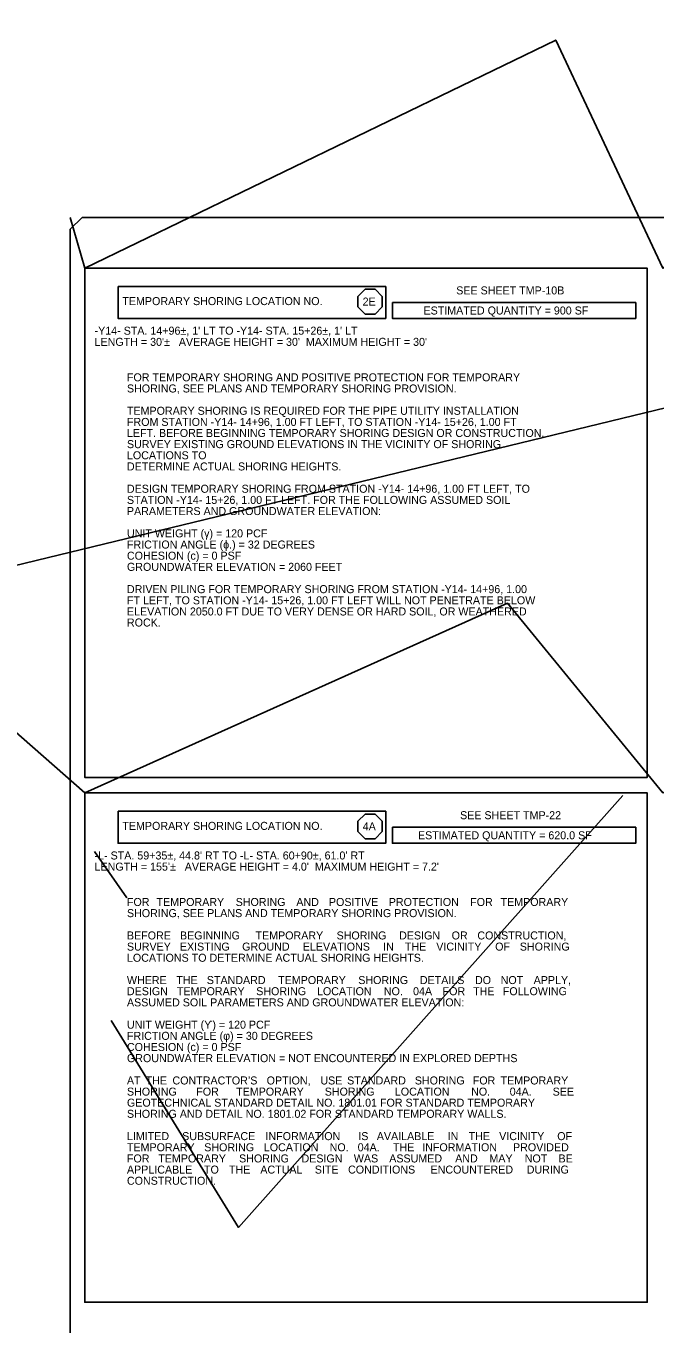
# Model space of a CAD drawing. Extents: x 2487012 to 2497594, y 369516 to 371986.
# Drawn here: x 2490762 to 2491299, y 370340 to 371445 of the extents above; entities that cross this region are included whole.
import ezdxf

# ---------------------------------------------------------------- set-up
doc = ezdxf.new("R2010")
doc.units = 0
for name, color, linetype in [('Scratch_Level_2', 7, 'Continuous'), ('Scratch_Level_3', 7, 'Continuous'), ('Scratch_Level_5', 7, 'Continuous'), ('Scratch_Level_6', 7, 'Continuous'), ('TC LABEL TEMP SHORING', 7, 'Continuous'), ('TC SHEET BORDER LINE THIN', 7, 'Continuous'), ('TC SHEET LAYOUT SHAPE', 7, 'Continuous'), ('TC SHEET TEXT', 7, 'Continuous')]:
    doc.layers.add(name, color=color, linetype=linetype)

msp = doc.modelspace()

# ---------------------------------------------------------------- linework, layer by layer
at = {"layer": 'Scratch_Level_2'}
msp.add_lwpolyline([(2490835.2, 370598.5), (2490943.8, 370422.2), (2491271.3, 370790.1)], dxfattribs=at)
at = {"layer": 'Scratch_Level_3'}
msp.add_line((2490800.3, 371282.3), (2490800.3, 371282.3), dxfattribs=at)
at = {"layer": 'Scratch_Level_5'}
msp.add_line((2490821, 370742.5), (2490848.6, 370702.8), dxfattribs=at)
at = {"layer": 'Scratch_Level_6'}
msp.add_lwpolyline([(2490800.3, 371282.3), (2490812.6, 371239.1), (2491214.2, 371433.4), (2491305.5, 371239.1), (2491620.3, 371445.4), (2491798.4, 371239.1), (2490627, 370955.2), (2490812.6, 370792.3), (2491172.9, 370953.9), (2491305.5, 370792.3), (2491661.6, 370924.6), (2491798.4, 370792.3)], dxfattribs=at)
at = {"layer": 'TC LABEL TEMP SHORING'}
for p, q in [((2491051.6, 371221.2), (2491045.5, 371215)), ((2491060.2, 371221.2), (2491051.6, 371221.2)), ((2491066.3, 371215), (2491060.2, 371221.2)), ((2491045.5, 371215), (2491045.5, 371206.3)), ((2491066.3, 371206.3), (2491066.3, 371215)), ((2491045.5, 371206.3), (2491051.6, 371200.1)), ((2491051.6, 371200.1), (2491060.2, 371200.1)), ((2491060.2, 371200.1), (2491066.3, 371206.3)), ((2491051.6, 370774.3), (2491045.5, 370768.1)), ((2491045.5, 370768.1), (2491045.5, 370759.4)), ((2491060.2, 370774.3), (2491051.6, 370774.3)), ((2491066.3, 370768.1), (2491060.2, 370774.3)), ((2491066.3, 370759.4), (2491066.3, 370768.1)), ((2491045.5, 370759.4), (2491051.6, 370753.2)), ((2491060.2, 370753.2), (2491066.3, 370759.4)), ((2491051.6, 370753.2), (2491060.2, 370753.2))]:
    msp.add_line(p, q, dxfattribs=at)
at = {"layer": 'TC SHEET BORDER LINE THIN'}
for points in [[(2490812.6, 371239.1), (2491292.1, 371239.1), (2491292.1, 370805.5), (2490812.6, 370805.5)], [(2490841.1, 371223.5), (2491069.2, 371223.5), (2491069.2, 371196.3), (2490841.1, 371196.3)], [(2491074.9, 371209.9), (2491282.4, 371209.9), (2491282.4, 371196.3), (2491074.9, 371196.3)], [(2490812.6, 370792.3), (2491292.1, 370792.3), (2491292.1, 370358.6), (2490812.6, 370358.6)], [(2490841.1, 370776.7), (2491069.2, 370776.7), (2491069.2, 370749.4), (2490841.1, 370749.4)], [(2491074.9, 370763), (2491282.4, 370763), (2491282.4, 370749.4), (2491074.9, 370749.4)]]:
    msp.add_lwpolyline(points, close=True, dxfattribs=at)
at = {"layer": 'TC SHEET LAYOUT SHAPE'}
msp.add_lwpolyline([(2490800.3, 370690.8), (2490800.3, 371000.2), (2490800.3, 371272.3), (2490810.3, 371282.3), (2491253.3, 371282.3), (2491724.3, 371282.3), (2492045.3, 371282.3), (2492045.3, 371202.3), (2492130.3, 371202.3), (2492130.3, 371250.3), (2492290.3, 371250.3), (2492290.3, 370915.3), (2492290.3, 370636.1), (2492290.3, 370384.8), (2491935.3, 370384.8), (2491935.3, 370242.3), (2491562.1, 370242.3), (2491392.7, 370242.3), (2491039.9, 370242.3), (2490800.3, 370242.3)], close=True, dxfattribs=at)

# ---------------------------------------------------------------- texts
at = {"layer": 'TC LABEL TEMP SHORING'}
for s, p in [('2E', (2491049.5, 371207.3)), ('4A', (2491049.6, 370760.4))]:
    msp.add_text(s, height=6.81, dxfattribs=at).set_placement(p)
at = {"layer": 'TC SHEET BORDER LINE THIN'}
for s, height, p in [('FOR TEMPORARY SHORING AND POSITIVE PROTECTION FOR TEMPORARY ', 6.814, (2490848.6, 371142.8)), ('SHORING, SEE PLANS AND TEMPORARY SHORING PROVISION.', 6.814, (2490848.6, 371133.3)), ('TEMPORARY SHORING IS REQUIRED FOR THE PIPE UTILITY INSTALLATION ', 6.814, (2490848.6, 371114.3)), ('FROM STATION -Y14- 14+96, 1.00 FT LEFT, TO STATION -Y14- 15+26, 1.00 FT ', 6.814, (2490848.6, 371104.8)), ('LEFT. BEFORE BEGINNING TEMPORARY SHORING DESIGN OR CONSTRUCTION, ', 6.814, (2490848.6, 371095.4)), ('SURVEY EXISTING GROUND ELEVATIONS IN THE VICINITY OF SHORING ', 6.814, (2490848.6, 371085.9)), ('LOCATIONS TO', 6.814, (2490848.6, 371076.4)), ('DETERMINE ACTUAL SHORING HEIGHTS.', 6.814, (2490848.6, 371066.9)), ('DESIGN TEMPORARY SHORING FROM STATION -Y14- 14+96, 1.00 FT LEFT, TO ', 6.814, (2490848.6, 371047.9)), ('STATION -Y14- 15+26, 1.00 FT LEFT. FOR THE FOLLOWING ASSUMED SOIL ', 6.814, (2490848.6, 371038.4)), ('PARAMETERS AND GROUNDWATER ELEVATION:', 6.814, (2490848.6, 371028.9)), ('UNIT WEIGHT (γ) = 120 PCF', 6.814, (2490848.6, 371009.9)), ('COHESION (c) = 0 PSF', 6.814, (2490848.6, 370990.9)), ('FRICTION ANGLE (ϕ.) = 32 DEGREES', 6.814, (2490848.6, 371000.4)), ('GROUNDWATER ELEVATION = 2060 FEET', 6.814, (2490848.6, 370981.4)), ('DRIVEN PILING FOR TEMPORARY SHORING FROM STATION -Y14- 14+96, 1.00 ', 6.814, (2490848.6, 370962.4)), ('FT LEFT, TO STATION -Y14- 15+26, 1.00 FT LEFT WILL NOT PENETRATE BELOW ', 6.814, (2490848.6, 370952.9)), ('ELEVATION 2050.0 FT DUE TO VERY DENSE OR HARD SOIL, OR WEATHERED ', 6.814, (2490848.6, 370943.4)), ('ROCK.', 6.81, (2490848.6, 370934)), ('FOR ', 6.81, (2490848.6, 370696)), ('TEMPORARY ', 6.81, (2490873.8, 370696)), ('SHORING ', 6.81, (2490941.3, 370696)), ('AND ', 6.81, (2490993, 370696)), ('POSITIVE ', 6.81, (2491020.8, 370696)), ('PROTECTION ', 6.814, (2491071.8, 370696)), ('FOR ', 6.81, (2491141.2, 370696)), ('TEMPORARY ', 6.81, (2491167.1, 370696)), ('SHORING, SEE PLANS AND TEMPORARY SHORING PROVISION.', 6.814, (2490848.6, 370686.5)), ('BEFORE ', 6.81, (2490848.6, 370667.5)), ('BEGINNING ', 6.81, (2490893.8, 370667.5)), ('TEMPORARY ', 6.81, (2490958.2, 370667.5)), ('SHORING ', 6.81, (2491027.3, 370667.5)), ('DESIGN ', 6.81, (2491080.6, 370667.5)), ('OR ', 6.81, (2491125.4, 370667.5)), ('CONSTRUCTION, ', 6.814, (2491147.3, 370667.5)), ('SURVEY ', 6.81, (2490848.6, 370658)), ('LOCATIONS TO DETERMINE ACTUAL SHORING HEIGHTS.', 6.814, (2490848.6, 370648.5)), ('EXISTING ', 6.81, (2490893.7, 370658)), ('GROUND ', 6.81, (2490946.8, 370658)), ('ELEVATIONS ', 6.814, (2490998.5, 370658)), ('IN ', 6.81, (2491067, 370658)), ('THE ', 6.81, (2491085.5, 370658)), ('VICINITY ', 6.81, (2491112.3, 370658)), ('OF ', 6.81, (2491162.5, 370658)), ('SHORING ', 6.81, (2491183.5, 370658)), ('WHERE ', 6.81, (2490848.6, 370629.5)), ('THE ', 6.81, (2490890.7, 370629.5)), ('STANDARD ', 6.81, (2490916.7, 370629.5)), ('TEMPORARY ', 6.81, (2490977.5, 370629.5)), ('SHORING ', 6.81, (2491045.8, 370629.5)), ('DETAILS ', 6.81, (2491098.3, 370629.5)), ('DO ', 6.81, (2491145.3, 370629.5)), ('NOT ', 6.81, (2491167.2, 370629.5)), ('APPLY, ', 6.81, (2491195.3, 370629.5)), ('DESIGN ', 6.81, (2490848.6, 370620)), ('TEMPORARY ', 6.81, (2490891.2, 370620)), ('SHORING ', 6.81, (2490958.8, 370620)), ('LOCATION ', 6.81, (2491010.6, 370620)), ('NO. ', 6.81, (2491067.6, 370620)), ('04A ', 6.81, (2491092.5, 370620)), ('FOR ', 6.81, (2491117.7, 370620)), ('THE ', 6.81, (2491143.7, 370620)), ('FOLLOWING ', 6.81, (2491169, 370620)), ('ASSUMED SOIL PARAMETERS AND GROUNDWATER ELEVATION:', 6.814, (2490848.6, 370610.5)), ('UNIT WEIGHT (ϒ) = 120 PCF ', 6.814, (2490848.6, 370591.5)), ('FRICTION ANGLE (φ) = 30 DEGREES ', 6.814, (2490848.6, 370582)), ('COHESION (c) = 0 PSF ', 6.814, (2490848.6, 370572.5)), ('GROUNDWATER ELEVATION = NOT ENCOUNTERED IN EXPLORED DEPTHS', 6.814, (2490848.6, 370563)), ('AT ', 6.81, (2490848.6, 370544)), ('THE ', 6.81, (2490864.5, 370544)), ('CONTRACTOR’S ', 6.814, (2490887.4, 370544)), ('OPTION, ', 6.81, (2490967.7, 370544)), ('USE ', 6.81, (2491013.5, 370544)), ('STANDARD ', 6.81, (2491036.3, 370544)), ('SHORING ', 6.81, (2491094, 370544)), ('FOR ', 6.81, (2491143.4, 370544)), ('TEMPORARY ', 6.81, (2491167.1, 370544)), ('SHORING ', 6.81, (2490848.6, 370534.5)), ('FOR ', 6.81, (2490907.7, 370534.5)), ('TEMPORARY ', 6.81, (2490941.7, 370534.5)), ('SHORING ', 6.81, (2491017.2, 370534.5)), ('LOCATION ', 6.81, (2491077, 370534.5)), ('NO. ', 6.81, (2491142, 370534.5)), ('04A. ', 6.81, (2491174.9, 370534.5)), ('SEE ', 6.81, (2491211.5, 370534.5)), ('SHORING AND DETAIL NO. 1801.02 FOR STANDARD TEMPORARY WALLS.', 6.814, (2490848.6, 370515.6)), ('GEOTECHNICAL STANDARD DETAIL NO. 1801.01 FOR STANDARD TEMPORARY ', 6.814, (2490848.6, 370525.1)), ('LIMITED ', 6.81, (2490848.6, 370496.6)), ('SUBSURFACE ', 6.814, (2490895.7, 370496.6)), ('INFORMATION ', 6.814, (2490966.7, 370496.6)), ('IS ', 6.81, (2491045.8, 370496.6)), ('AVAILABLE ', 6.81, (2491061.6, 370496.6)), ('IN ', 6.81, (2491122, 370496.6)), ('THE ', 6.81, (2491139.9, 370496.6)), ('VICINITY ', 6.81, (2491165.9, 370496.6)), ('OF ', 6.81, (2491215.4, 370496.6)), ('TEMPORARY ', 6.81, (2490848.6, 370487.1)), ('SHORING ', 6.81, (2490914.5, 370487.1)), ('LOCATION ', 6.81, (2490965.3, 370487.1)), ('NO. ', 6.81, (2491021.4, 370487.1)), ('04A. ', 6.81, (2491045.3, 370487.1)), (' THE ', 6.81, (2491072.9, 370487.1)), ('INFORMATION ', 6.814, (2491100.3, 370487.1)), ('PROVIDED ', 6.81, (2491177.7, 370487.1)), ('FOR ', 6.81, (2490848.6, 370477.6)), ('TEMPORARY ', 6.81, (2490875.3, 370477.6)), ('SHORING ', 6.81, (2490944.2, 370477.6)), ('DESIGN ', 6.81, (2490997.4, 370477.6)), ('WAS ', 6.81, (2491042, 370477.6)), ('ASSUMED ', 6.81, (2491072.2, 370477.6)), ('AND ', 6.81, (2491128.4, 370477.6)), ('MAY ', 6.81, (2491157.6, 370477.6)), ('NOT ', 6.81, (2491187.7, 370477.6)), ('BE ', 6.81, (2491216.5, 370477.6)), ('APPLICABLE ', 6.814, (2490848.6, 370468.1)), ('TO ', 6.81, (2490914.3, 370468.1)), ('THE ', 6.81, (2490935.6, 370468.1)), ('ACTUAL ', 6.81, (2490962.3, 370468.1)), ('SITE ', 6.81, (2491008.7, 370468.1)), ('CONDITIONS ', 6.814, (2491037.1, 370468.1)), ('ENCOUNTERED ', 6.814, (2491107.4, 370468.1)), ('DURING ', 6.81, (2491189.4, 370468.1)), ('CONSTRUCTION.', 6.814, (2490848.6, 370458.6))]:
    msp.add_text(s, height=height, dxfattribs=at).set_placement(p)
at = {"layer": 'TC SHEET TEXT'}
for s, p in [('SEE SHEET TMP-10B', (2491129.3, 371216.8)), ('TEMPORARY SHORING LOCATION NO.', (2490844.7, 371207.7)), ('ESTIMATED QUANTITY = 900 SF', (2491101.4, 371199.7)), ("-Y14- STA. 14+96±, 1' LT TO -Y14- STA. 15+26±, 1' LT", (2490821, 371182.5)), ("LENGTH = 30'±   AVERAGE HEIGHT = 30'  MAXIMUM HEIGHT = 30'", (2490821, 371173)), ('SEE SHEET TMP-22', (2491132.6, 370769.9)), ('TEMPORARY SHORING LOCATION NO.', (2490844.7, 370760.8)), ('ESTIMATED QUANTITY = 620.0 SF', (2491096.7, 370752.8)), ("-L- STA. 59+35±, 44.8' RT TO -L- STA. 60+90±, 61.0' RT", (2490821, 370735.6)), ("LENGTH = 155'±   AVERAGE HEIGHT = 4.0'  MAXIMUM HEIGHT = 7.2'", (2490821, 370726.1))]:
    msp.add_text(s, height=6.814, dxfattribs=at).set_placement(p)

doc.saveas('drawing.dxf')
